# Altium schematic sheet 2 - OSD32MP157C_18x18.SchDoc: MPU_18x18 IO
size A3; DocumentNumber: DK2 RefDes; Revision: C-01; SheetNumber: 2; SheetTotal: 14
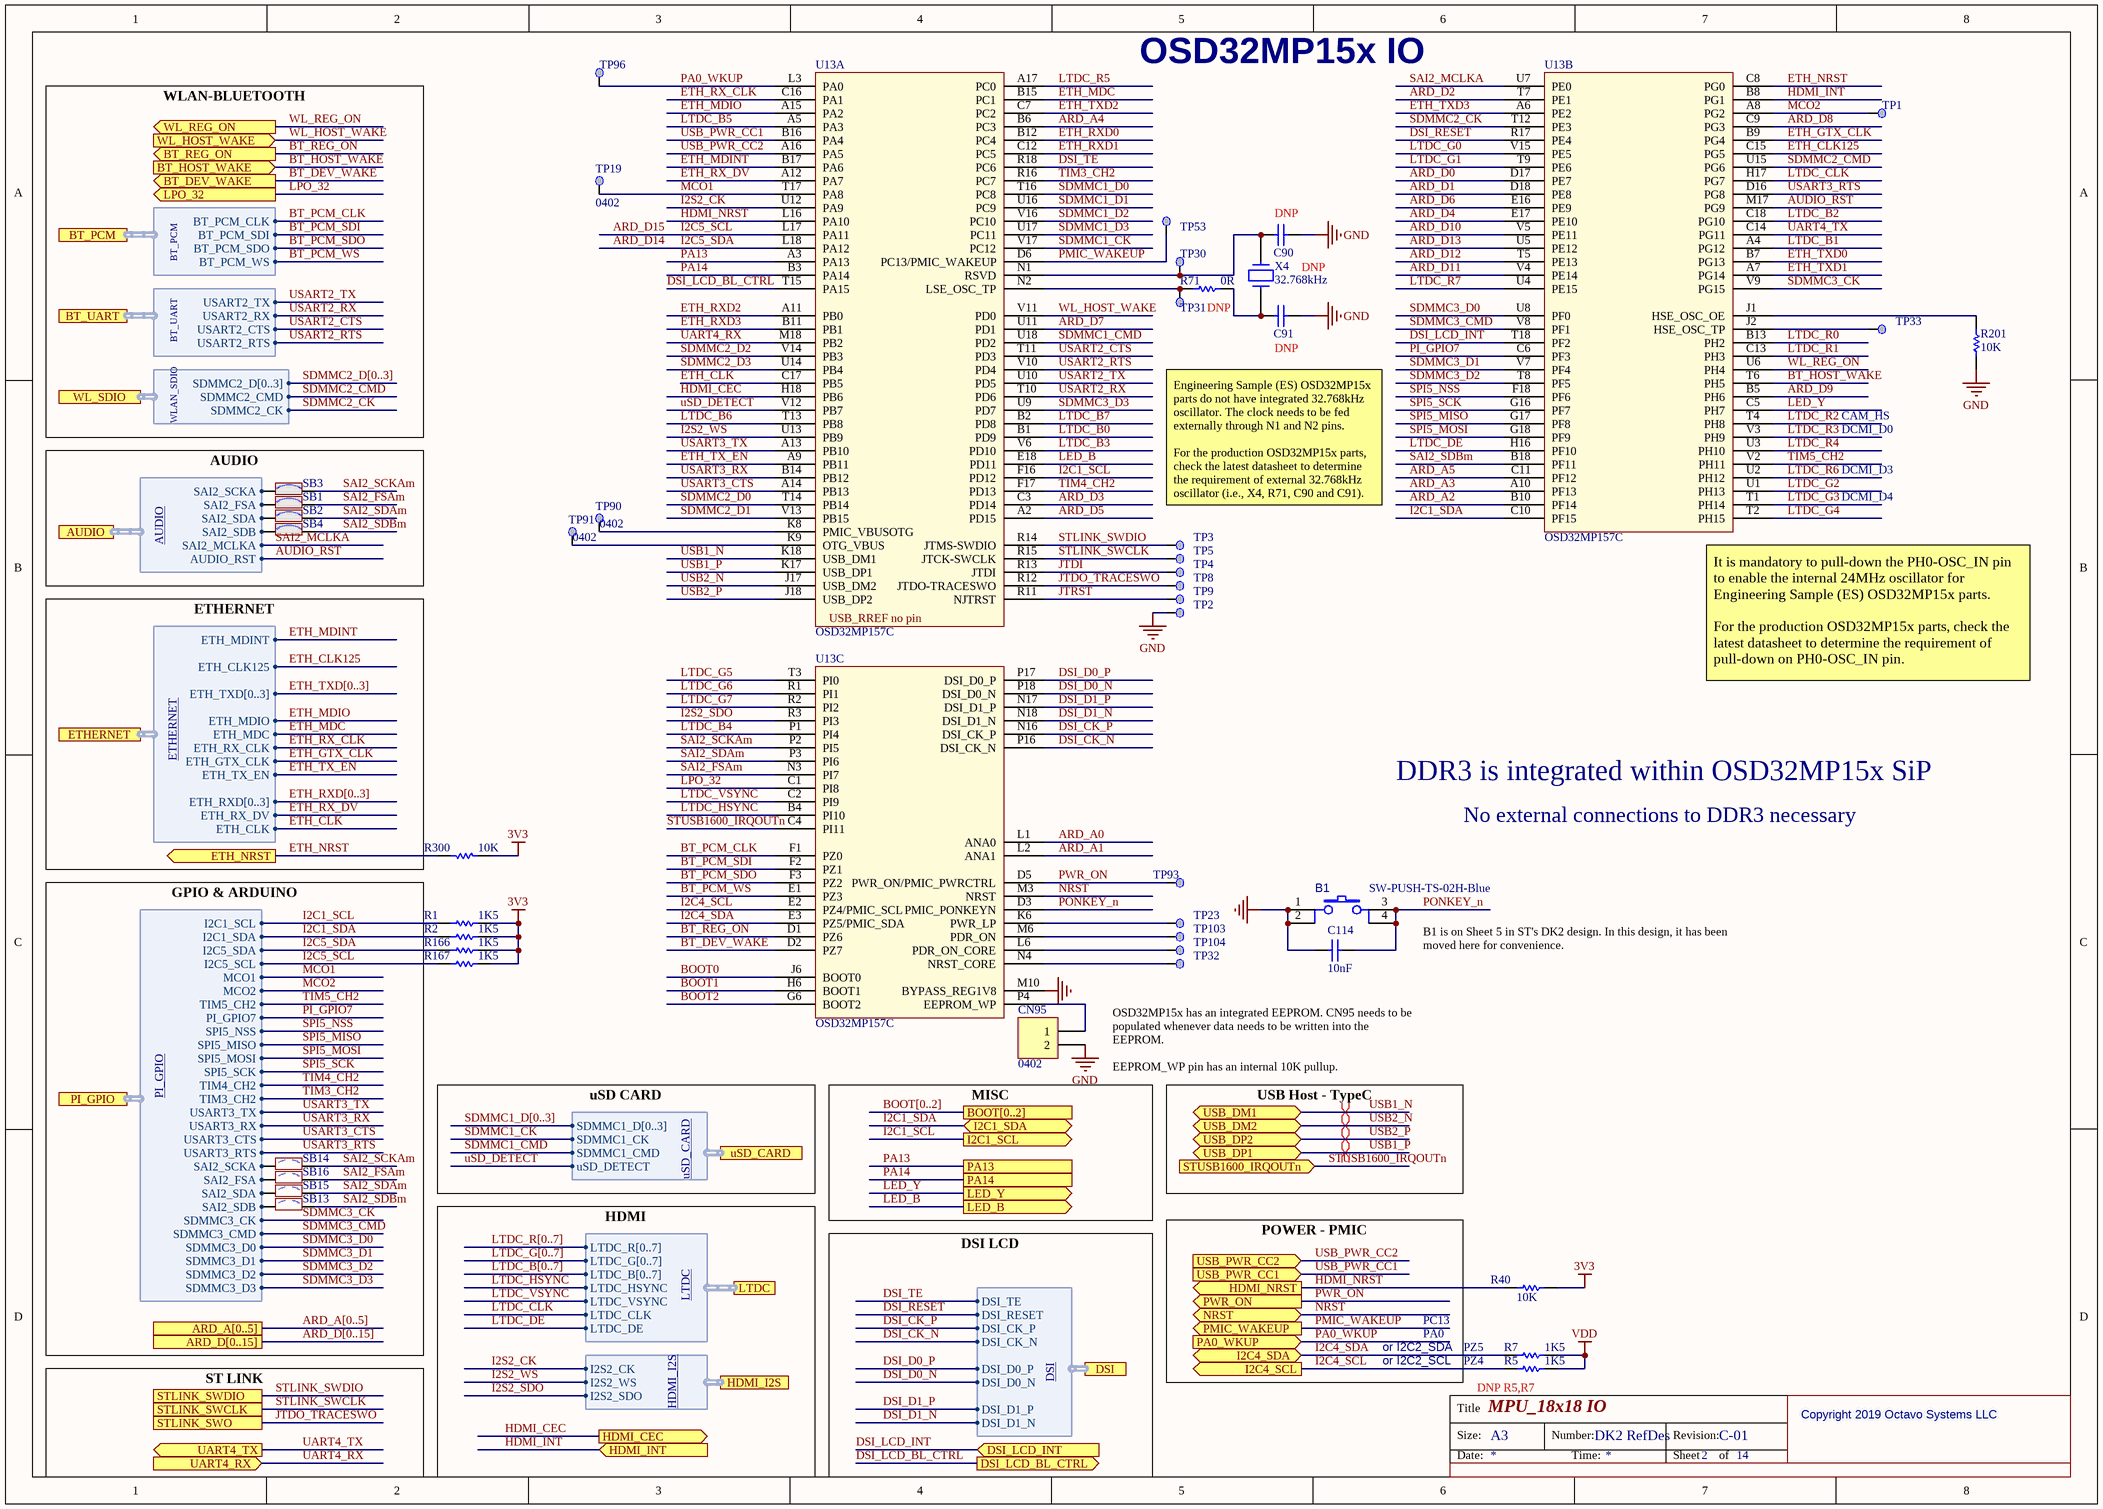
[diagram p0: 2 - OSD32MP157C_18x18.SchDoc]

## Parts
B1  value SW-PUSH-TS-02H-Blue  [SWI_JIUBABA_C-TS-02H-2-5-B-V-T_R_BLUE]
C90  Capacitor  [C0402]  (value not drawn)  (no BOM)
C91  Capacitor  [C0402]  (value not drawn)  (no BOM)
C114  value 10nF  [C0402]
CN95  0402  [MHDR1X2]
R1  value 1K5  [R0402]
R2  value 1K5  [R0402]
R5  value 1K5  [R0402]  (no BOM)
R7  value 1K5  [R0402]  (no BOM)
R40  value 10K  [R0402]  (hidden comment: Resistor)
R71  value 0R  [R0402]
R166  value 1K5  [R0402]
R167  value 1K5  [R0402]
R201  value 10K  [R0402]
R300  value 10K  [R0402]  (hidden comment: Resistor)
SB1  (no value)  [SOLDER-BRIDGE_R0603-0R]
SB2  (no value)  [SOLDER-BRIDGE_R0603-0R]
SB3  (no value)  [SOLDER-BRIDGE_R0603-0R]
SB4  (no value)  [SOLDER-BRIDGE_R0603-0R]
SB13  (no value)  [SOLDER-BRIDGE_R0603-0R]
SB14  (no value)  [SOLDER-BRIDGE_R0603-0R]
SB15  (no value)  [SOLDER-BRIDGE_R0603-0R]
SB16  (no value)  [SOLDER-BRIDGE_R0603-0R]
TP1  Test Point  [TP_SMD_1MM]  (value not drawn)  (no BOM)
TP2  Test Point  [TP_SMD_1MM]  (value not drawn)  (no BOM)
TP3  Test Point  [TP_SMD_1MM]  (value not drawn)  (no BOM)
TP4  Test Point  [TP_SMD_1MM]  (value not drawn)  (no BOM)
TP5  Test Point  [TP_SMD_1MM]  (value not drawn)  (no BOM)
TP8  Test Point  [TP_SMD_1MM]  (value not drawn)  (no BOM)
TP9  Test Point  [TP_SMD_1MM]  (value not drawn)  (no BOM)
TP19  0402  [TP]
TP23  Test Point  [TP_SMD_1MM]  (value not drawn)  (no BOM)
TP30  Test Point  [TP_SMD_1MM]  (value not drawn)  (no BOM)
TP31  Test Point  [TP_SMD_1MM]  (value not drawn)  (no BOM)
TP32  Test Point  [TP_SMD_1MM]  (value not drawn)  (no BOM)
TP33  Test Point  [TP_SMD_1MM]  (value not drawn)  (no BOM)
TP53  0402  [TP]  (value not drawn)
TP90  0402  [TP]
TP91  0402  [TP]
TP93  0402  [TP]  (value not drawn)
TP96  0402  [TP]  (value not drawn)
TP103  0402  [TP]  (value not drawn)
TP104  0402  [TP]  (value not drawn)
U13  OSD32MP157C  [ICC_BGA324_18X18_OSD32MP157CAC3]  (parts A,B,C of 4)
X4  value 32.768kHz  [CRY_NX2012SA_2P]

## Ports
ARD_A[0..5], ARD_D[0..15], AUDIO (harness AUDIO), BOOT[0..2], BT_DEV_WAKE (out), BT_HOST_WAKE (in), BT_PCM (harness BT_PCM), BT_REG_ON (out), BT_UART (harness BT_UART), DSI (harness DSI), DSI_LCD_BL_CTRL (out), DSI_LCD_INT (in), ETH_NRST (out), ETHERNET (harness ETHERNET), HDMI_CEC (out), HDMI_I2S (harness HDMI_I2S), HDMI_INT (in), HDMI_NRST (out), I2C1_SCL (out), I2C1_SDA (bidir), I2C4_SCL (out), I2C4_SDA (bidir), LED_B (out), LED_Y (out), LPO_32 (out), LTDC (harness LTDC), NRST (bidir), PA0_WKUP (in), PA13, PA14, PI_GPIO (harness PI_GPIO), PMIC_WAKEUP (out), PWR_ON (out), STLINK_SWCLK, STLINK_SWDIO, STLINK_SWO, STUSB1600_IRQOUTn (in), UART4_RX (in), UART4_TX (out), USB_DM1 (bidir), USB_DM2 (bidir), USB_DP1 (bidir), USB_DP2 (bidir), USB_PWR_CC1 (in), USB_PWR_CC2 (in), uSD_CARD (harness uSD_CARD), WL_HOST_WAKE (in), WL_REG_ON (out), WL_SDIO (harness WLAN_SDIO)

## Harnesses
PI_GPIO: I2C1_SCL, I2C1_SDA, I2C5_SDA, MCO1, MCO2, TIM5_CH2, PI_GPIO7, SPI5_NSS, SPI5_MISO, SPI5_MOSI, SPI5_SCK, TIM4_CH2, TIM3_CH2, USART3_TX, USART3_RX, USART3_CTS, USART3_RTS, SDMMC3_CK, SDMMC3_CMD, SDMMC3_D0, SDMMC3_D1, SDMMC3_D2, SDMMC3_D3, I2C5_SCL, SAI2_SCKA, SAI2_FSA, SAI2_SDA, SAI2_SDB
ETHERNET: ETH_MDINT, ETH_CLK125, ETH_TXD[0..3], ETH_MDIO, ETH_MDC, ETH_RX_CLK, ETH_GTX_CLK, ETH_TX_EN, ETH_RXD[0..3], ETH_RX_DV, ETH_CLK
AUDIO: SAI2_SCKA, SAI2_FSA, SAI2_SDA, SAI2_SDB, SAI2_MCLKA, AUDIO_RST
LTDC: LTDC_R[0..7], LTDC_G[0..7], LTDC_B[0..7], LTDC_HSYNC, LTDC_VSYNC, LTDC_CLK, LTDC_DE
uSD_CARD: SDMMC1_D[0..3], SDMMC1_CK, SDMMC1_CMD, uSD_DETECT
BT_PCM: BT_PCM_CLK, BT_PCM_SDI, BT_PCM_SDO, BT_PCM_WS
BT_UART: USART2_TX, USART2_RX, USART2_CTS, USART2_RTS
WLAN_SDIO: SDMMC2_D[0..3], SDMMC2_CMD, SDMMC2_CK
HDMI_I2S: I2S2_CK, I2S2_SDO, I2S2_WS
DSI: DSI_CK_P, DSI_CK_N, DSI_D0_P, DSI_D0_N, DSI_D1_P, DSI_D1_N, DSI_TE, DSI_RESET

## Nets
3V3: R1.1 R2.1 R40.1 R166.1 R167.1 R300.1
GND: B1.1 B1.2 C90.2 C91.2 C114.1 CN95.2 R201.1 TP2.1 U13.M10(BYPASS_REG1V8)
VDD: R5.1 R7.1
ARD_A0: U13.L1(ANA0)
ARD_A1: U13.L2(ANA1)
ARD_A2: U13.B10(PF14)
ARD_A3: U13.A10(PF13)
ARD_A4: U13.B6(PC3)
ARD_A5: U13.C11(PF12)
ARD_D0: U13.D17(PE7)
ARD_D1: U13.D18(PE8)
ARD_D2: U13.T7(PE1)
ARD_D3: U13.C3(PD14)
ARD_D4: U13.E17(PE10)
ARD_D5: U13.A2(PD15)
ARD_D6: U13.E16(PE9)
ARD_D7: U13.U11(PD1)
ARD_D8: U13.C9(PG3)
ARD_D9: U13.B5(PH6)
ARD_D10: U13.V5(PE11)
ARD_D11: U13.V4(PE14)
ARD_D12: U13.T5(PE13)
ARD_D13: U13.U5(PE12)
ARD_D14: R166.2 U13.L18(PA12) ; port PI_GPIO.I2C5_SDA  [also labelled I2C5_SDA]
ARD_D15: R167.2 U13.L17(PA11) ; port PI_GPIO.I2C5_SCL  [also labelled I2C5_SCL]
AUDIO_RST: U13.M17(PG9) ; port AUDIO.AUDIO_RST
BOOT0: U13.J6(BOOT0)
BOOT1: U13.H6(BOOT1)
BOOT2: U13.G6(BOOT2)
BT_DEV_WAKE: U13.D2(PZ7) ; port BT_DEV_WAKE
BT_HOST_WAKE: U13.T6(PH5) ; port BT_HOST_WAKE
BT_PCM_CLK: U13.F1(PZ0) ; port BT_PCM.BT_PCM_CLK
BT_PCM_SDI: U13.F2(PZ1) ; port BT_PCM.BT_PCM_SDI
BT_PCM_SDO: U13.F3(PZ2) ; port BT_PCM.BT_PCM_SDO
BT_PCM_WS: U13.E1(PZ3) ; port BT_PCM.BT_PCM_WS
BT_REG_ON: U13.D1(PZ6) ; port BT_REG_ON
DSI_CK_N: U13.P16(DSI_CK_N) ; port DSI.DSI_CK_N
DSI_CK_P: U13.N16(DSI_CK_P) ; port DSI.DSI_CK_P
DSI_D0_N: U13.P18(DSI_D0_N) ; port DSI.DSI_D0_N
DSI_D0_P: U13.P17(DSI_D0_P) ; port DSI.DSI_D0_P
DSI_D1_N: U13.N18(DSI_D1_N) ; port DSI.DSI_D1_N
DSI_D1_P: U13.N17(DSI_D1_P) ; port DSI.DSI_D1_P
DSI_LCD_BL_CTRL: U13.T15(PA15) ; port DSI_LCD_BL_CTRL
DSI_LCD_INT: U13.T18(PF2) ; port DSI_LCD_INT
DSI_RESET: U13.R17(PE4) ; port DSI.DSI_RESET
DSI_TE: U13.R18(PC6) ; port DSI.DSI_TE
ETH_CLK: U13.C17(PB5) ; port ETHERNET.ETH_CLK
ETH_CLK125: U13.C15(PG5) ; port ETHERNET.ETH_CLK125
ETH_GTX_CLK: U13.B9(PG4) ; port ETHERNET.ETH_GTX_CLK
ETH_MDC: U13.B15(PC1) ; port ETHERNET.ETH_MDC
ETH_MDINT: U13.B17(PA6) ; port ETHERNET.ETH_MDINT
ETH_MDIO: U13.A15(PA2) ; port ETHERNET.ETH_MDIO
ETH_NRST: R300.2 U13.C8(PG0) ; port ETH_NRST
ETH_RX_CLK: U13.C16(PA1) ; port ETHERNET.ETH_RX_CLK
ETH_RX_DV: U13.A12(PA7) ; port ETHERNET.ETH_RX_DV
ETH_RXD0: U13.B12(PC4)
ETH_RXD1: U13.C12(PC5)
ETH_RXD2: U13.A11(PB0)
ETH_RXD3: U13.B11(PB1)
ETH_TX_EN: U13.A9(PB11) ; port ETHERNET.ETH_TX_EN
ETH_TXD0: U13.B7(PG13)
ETH_TXD1: U13.A7(PG14)
ETH_TXD2: U13.C7(PC2)
ETH_TXD3: U13.A6(PE2)
HDMI_CEC: U13.H18(PB6) ; port HDMI_CEC
HDMI_INT: U13.B8(PG1) ; port HDMI_INT
HDMI_NRST: R40.2 U13.L16(PA10) ; port HDMI_NRST
I2C1_SCL: R1.2 U13.F16(PD12) ; port I2C1_SCL, port PI_GPIO.I2C1_SCL
I2C1_SDA: R2.2 U13.C10(PF15) ; port I2C1_SDA, port PI_GPIO.I2C1_SDA
I2C4_SCL: R5.2 U13.E2(PZ4/PMIC_SCL) ; port I2C4_SCL
I2C4_SDA: R7.2 U13.E3(PZ5/PMIC_SDA) ; port I2C4_SDA
I2S2_CK: U13.U12(PA9) ; port HDMI_I2S.I2S2_CK
I2S2_SDO: U13.R3(PI3) ; port HDMI_I2S.I2S2_SDO
I2S2_WS: U13.U13(PB9) ; port HDMI_I2S.I2S2_WS
JTDI: TP4.1 U13.R13(JTDI)
JTDO_TRACESWO: TP8.1 U13.R12(JTDO-TRACESWO) ; port STLINK_SWO
JTRST: TP9.1 U13.R11(NJTRST)
LED_B: U13.E18(PD11) ; port LED_B
LED_Y: U13.C5(PH7) ; port LED_Y
LPO_32: U13.C1(PI8) ; port LPO_32
LTDC_B0: U13.B1(PD9)
LTDC_B1: U13.A4(PG12)
LTDC_B2: U13.C18(PG10)
LTDC_B3: U13.V6(PD10)
LTDC_B4: U13.P1(PI4)
LTDC_B5: U13.A5(PA3)
LTDC_B6: U13.T13(PB8)
LTDC_B7: U13.B2(PD8)
LTDC_CLK: U13.H17(PG7) ; port LTDC.LTDC_CLK
LTDC_DE: U13.H16(PF10) ; port LTDC.LTDC_DE
LTDC_G0: U13.V15(PE5)
LTDC_G1: U13.T9(PE6)
LTDC_G2: U13.U1(PH13)
LTDC_G3: U13.T1(PH14)
LTDC_G4: U13.T2(PH15)
LTDC_G5: U13.T3(PI0)
LTDC_G6: U13.R1(PI1)
LTDC_G7: U13.R2(PI2)
LTDC_HSYNC: U13.B4(PI10) ; port LTDC.LTDC_HSYNC
LTDC_R0: U13.B13(PH2)
LTDC_R1: U13.C13(PH3)
LTDC_R2: U13.T4(PH8)
LTDC_R3: U13.V3(PH9)
LTDC_R4: U13.U3(PH10)
LTDC_R5: U13.A17(PC0)
LTDC_R6: U13.U2(PH12)
LTDC_R7: U13.U4(PE15)
LTDC_VSYNC: U13.C2(PI9) ; port LTDC.LTDC_VSYNC
MCO1: TP19.1 U13.T17(PA8) ; port PI_GPIO.MCO1
MCO2: TP1.1 U13.A8(PG2) ; port PI_GPIO.MCO2
NRST: U13.M3(NRST) ; port NRST
PA0_WKUP: TP96.1 U13.L3(PA0) ; port PA0_WKUP
PA13: U13.A3(PA13) ; port PA13
PA14: U13.B3(PA14) ; port PA14
PI_GPIO7: U13.C6(PF3) ; port PI_GPIO.PI_GPIO7
PMIC_WAKEUP: TP53.1 U13.D6(PC13/PMIC_WAKEUP) ; port PMIC_WAKEUP
PONKEY_n: B1.3 B1.4 C114.2 U13.D3(PMIC_PONKEYN)
PWR_ON: TP93.1 U13.D5(PWR_ON/PMIC_PWRCTRL) ; port PWR_ON
SAI2_FSAm: SB1.2 SB16.2 U13.N3(PI7)
SAI2_MCLKA: U13.U7(PE0) ; port AUDIO.SAI2_MCLKA
SAI2_SCKAm: SB3.2 SB14.2 U13.P2(PI5)
SAI2_SDAm: SB2.2 SB15.2 U13.P3(PI6)
SAI2_SDBm: SB4.2 SB13.2 U13.B18(PF11)
SDMMC1_CK: U13.V17(PC12) ; port uSD_CARD.SDMMC1_CK
SDMMC1_CMD: U13.U18(PD2) ; port uSD_CARD.SDMMC1_CMD
SDMMC1_D0: U13.T16(PC8)
SDMMC1_D1: U13.U16(PC9)
SDMMC1_D2: U13.V16(PC10)
SDMMC1_D3: U13.U17(PC11)
SDMMC2_CK: U13.T12(PE3) ; port WL_SDIO.SDMMC2_CK
SDMMC2_CMD: U13.U15(PG6) ; port WL_SDIO.SDMMC2_CMD
SDMMC2_D0: U13.T14(PB14)
SDMMC2_D1: U13.V13(PB15)
SDMMC2_D2: U13.V14(PB3)
SDMMC2_D3: U13.U14(PB4)
SDMMC3_CK: U13.V9(PG15) ; port PI_GPIO.SDMMC3_CK
SDMMC3_CMD: U13.V8(PF1) ; port PI_GPIO.SDMMC3_CMD
SDMMC3_D0: U13.U8(PF0) ; port PI_GPIO.SDMMC3_D0
SDMMC3_D1: U13.V7(PF4) ; port PI_GPIO.SDMMC3_D1
SDMMC3_D2: U13.T8(PF5) ; port PI_GPIO.SDMMC3_D2
SDMMC3_D3: U13.U9(PD7) ; port PI_GPIO.SDMMC3_D3
SPI5_MISO: U13.G17(PF8) ; port PI_GPIO.SPI5_MISO
SPI5_MOSI: U13.G18(PF9) ; port PI_GPIO.SPI5_MOSI
SPI5_NSS: U13.F18(PF6) ; port PI_GPIO.SPI5_NSS
SPI5_SCK: U13.G16(PF7) ; port PI_GPIO.SPI5_SCK
STLINK_SWCLK: TP5.1 U13.R15(JTCK-SWCLK) ; port STLINK_SWCLK
STLINK_SWDIO: TP3.1 U13.R14(JTMS-SWDIO) ; port STLINK_SWDIO
STUSB1600_IRQOUTn: U13.C4(PI11) ; port STUSB1600_IRQOUTn
TIM3_CH2: U13.R16(PC7) ; port PI_GPIO.TIM3_CH2
TIM4_CH2: U13.F17(PD13) ; port PI_GPIO.TIM4_CH2
TIM5_CH2: U13.V2(PH11) ; port PI_GPIO.TIM5_CH2
UART4_RX: U13.M18(PB2) ; port UART4_RX
UART4_TX: U13.C14(PG11) ; port UART4_TX
USART2_CTS: U13.T11(PD3) ; port BT_UART.USART2_CTS
USART2_RTS: U13.V10(PD4) ; port BT_UART.USART2_RTS
USART2_RX: U13.T10(PD6) ; port BT_UART.USART2_RX
USART2_TX: U13.U10(PD5) ; port BT_UART.USART2_TX
USART3_CTS: U13.A14(PB13) ; port PI_GPIO.USART3_CTS
USART3_RTS: U13.D16(PG8) ; port PI_GPIO.USART3_RTS
USART3_RX: U13.B14(PB12) ; port PI_GPIO.USART3_RX
USART3_TX: U13.A13(PB10) ; port PI_GPIO.USART3_TX
USB1_N: U13.K18(USB_DM1) ; port USB_DM1
USB1_P: U13.K17(USB_DP1) ; port USB_DP1
USB2_N: U13.J17(USB_DM2) ; port USB_DM2
USB2_P: U13.J18(USB_DP2) ; port USB_DP2
USB_PWR_CC1: U13.B16(PA4) ; port USB_PWR_CC1
USB_PWR_CC2: U13.A16(PA5) ; port USB_PWR_CC2
uSD_DETECT: U13.V12(PB7) ; port uSD_CARD.uSD_DETECT
WL_HOST_WAKE: U13.V11(PD0) ; port WL_HOST_WAKE
WL_REG_ON: U13.U6(PH4) ; port WL_REG_ON
NetC90_1: C90.1 TP30.1 U13.N1(RSVD) X4.1
NetC91_1: C91.1 R71.2 X4.2
NetCN95_1: CN95.1 U13.P4(EEPROM_WP)
NetR71_1: R71.1 TP31.1 U13.N2(LSE_OSC_TP)
NetR201_2: R201.2 U13.J1(HSE_OSC_OE)
NetSB1_1: SB1.1 ; port AUDIO.SAI2_FSA
NetSB2_1: SB2.1 ; port AUDIO.SAI2_SDA
NetSB3_1: SB3.1 ; port AUDIO.SAI2_SCKA
NetSB4_1: SB4.1 ; port AUDIO.SAI2_SDB
NetSB13_1: SB13.1 ; port PI_GPIO.SAI2_SDB
NetSB14_1: SB14.1 ; port PI_GPIO.SAI2_SCKA
NetSB15_1: SB15.1 ; port PI_GPIO.SAI2_SDA
NetSB16_1: SB16.1 ; port PI_GPIO.SAI2_FSA
NetTP23_1: TP23.1 U13.K6(PWR_LP)
NetTP32_1: TP32.1 U13.N4(NRST_CORE)
NetTP33_1: TP33.1 U13.J2(HSE_OSC_TP)
NetTP90_1: TP90.1 U13.K8(PMIC_VBUSOTG)
NetTP91_1: TP91.1 U13.K9(OTG_VBUS)
NetTP103_1: TP103.1 U13.M6(PDR_ON)
NetTP104_1: TP104.1 U13.L6(PDR_ON_CORE)

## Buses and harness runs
bus ARD_A[0..5] = port ARD_A[0..5]
bus ARD_D[0..15] = port ARD_D[0..15]
bus BOOT[0..2] = port BOOT[0..2]
bus ETH_RXD[0..3]
bus ETH_TXD[0..3]
bus LTDC_B[0..7]
bus LTDC_G[0..7]
bus LTDC_R[0..7]
bus SDMMC1_D[0..3]
bus SDMMC2_D[0..3]

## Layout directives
differential pair: USB1_N, USB1_P, USB2_N, USB2_P

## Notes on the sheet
- OSD32MP15x IO
- (near C90) DNP
- (near R71) DNP
- DNP
- (near C91) DNP
- WLAN-BLUETOOTH
- DCMI_D0
- CAM_HS
- Engineering Sample (ES) OSD32MP15x parts do not have integrated 32.768kHz oscillator. The clock needs to be fed externally through N1 and N2 pins.
  For the production OSD32MP15x parts, check the latest datasheet to determine the requirement of external 32.768kHz oscillator (i.e., X4, R71, C90 and C91).
- DCMI_D3
- DCMI_D4
- AUDIO
- (near U13) It is mandatory to pull-down the PH0-OSC_IN pin to enable the internal 24MHz oscillator for Engineering Sample (ES) OSD32MP15x parts.
  For the production OSD32MP15x parts, check the latest datasheet to determine the requirement of  pull-down on PH0-OSC_IN pin.
- DDR3 is integrated within OSD32MP15x SiP
- No external connections to DDR3 necessary
- (near R300) ETHERNET
- B1 is on Sheet 5 in ST's DK2 design. In this design, it has been moved here for convenience.
- OSD32MP15x has an integrated EEPROM. CN95 needs to be populated whenever data needs to be written into the EEPROM.
  EEPROM_WP pin has an internal 10K pullup.
- uSD CARD
- USB Host - TypeC
- (near CN95) MISC
- PC13
- GPIO & ARDUINO
- POWER - PMIC
- or I2C2_SDA
- or I2C2_SCL
- PA0
- PZ5
- PZ4
- (near R5) DNP R5,R7
- Copyright 2019 Octavo Systems LLC
- ST LINK
- HDMI
- DSI LCD

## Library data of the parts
B1 = MCD-00172: Switch HW SMD blue; Part_Type: Misc; Manufacturer_Part_Number: C-TS-02H-2.5-B-V-T/R BLUE; Manufacturer: JIUBABA; Provided_By: Subcon; Initial_Board_Reference: MB1264
C90 C91 = MCD-00200: Capacitor, MLCC, 12pF, 50V, NPO, 5%, 0402, T=0,5mm; Manufacturer_Part_Number: CC0402JRNPO9BN120; Manufacturer: YAGEO; Provided_By: Subcon
C114 = MCD-00011: Capacitor, MLCC, 10nF, 16V, X7R, 10%, 0402, T=0.5mm; Manufacturer_Part_Number: CC0402KRX7R7BB103; Manufacturer: YAGEO; Provided_By: Subcon; Initial_Board_Reference: mb1274
CN95 = MHDR1x2: Header, 2-Pin, 50 mil
R1 R2 R5 R7 R166 R167 = MCD-00068: Resistor,1K5,0402,1%,1/16W; Manufacturer_Part_Number: RC0402FR-071K5L; Manufacturer: YAGEO; Provided_By: Subcon; Initial_Board_Reference: mb1274
R40 R300 = MCD-00053: Resistor,10K,0402,1%,1/16W; Manufacturer_Part_Number: RC0402FR-0710KL; Manufacturer: YAGEO; Provided_By: subcon; Initial_Board_Reference: MB1274
R71 = MCD-00052: Resistor,0R,0402,5%,1/16W; Manufacturer_Part_Number: RC0402JR-070RL; Manufacturer: YAGEO; Provided_By: Subcon; Initial_Board_Reference: mb1274
R201 = MCD-00185: Resistor,3K,0402,1%,1/16W; Manufacturer_Part_Number: RC0402FR-073KL; Manufacturer: YAGEO; Provided_By: Subcon
SB1-SB4 = MCD-00071: Solder Bridge ON; Part_Type: Mechanical; Provided_By: Subcon; Initial_Board_Reference: mb1274
SB13-SB16 = MCD-00072: Solder Bridge OFF; Part_Type: Mechanical; Initial_Board_Reference: mb1274
TP1-TP5 TP8 TP9 TP23 TP30-TP33 = MCD-00074: Test Point 1mm; Part_Type: Mechanical; Initial_Board_Reference: MB1274
TP19 TP53 TP90 TP91 TP93 TP96 TP103 TP104 = TP: Testpoint
U13 = OSD32MP157C: MPU 18x18 SIP; Part_Type: IC; Manufacturer: Octavo; ECCN_US: TBD
X4 = MCD-00292: Surface mount Crystal 32.768kHz, 12.5pF; Manufacturer_Part_Number: NX2012SA 32.768kHz EXS00A-MU00528; Part_Type: Crystal_Osc; Manufacturer: NDK; Provided_By: Subcon; Initial_Board_Reference: MB1263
